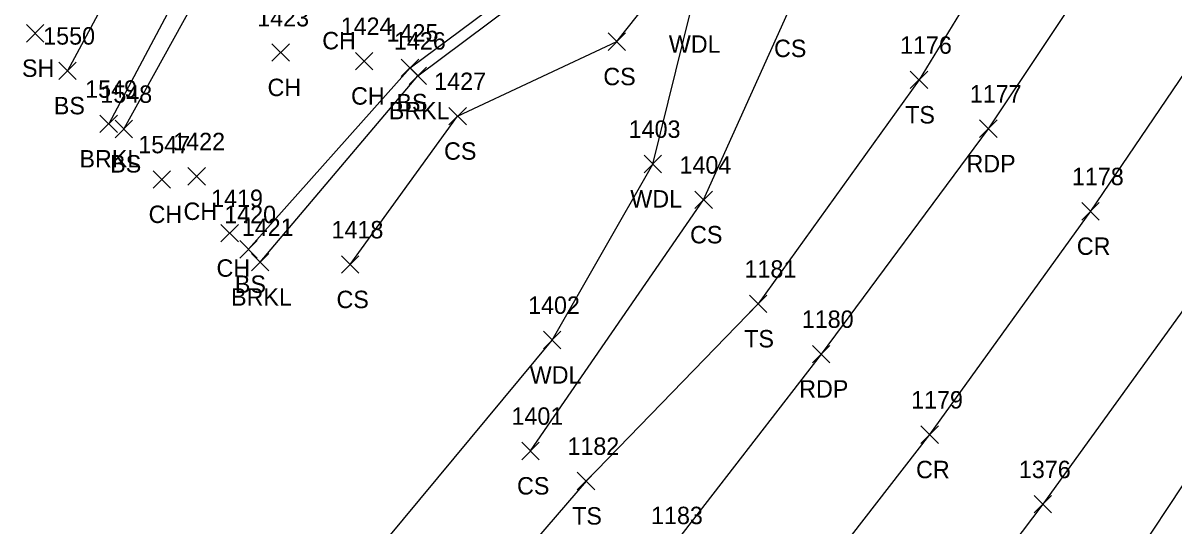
# Model space of a CAD drawing. Extents: x 1599840 to 1601211, y 518904 to 521989.
# Drawn here: x 1600682.8 to 1600815, y 521188.3 to 521246 of the extents above; entities that cross this region are included whole.
import ezdxf

# ---------------------------------------------------------------- set-up
doc = ezdxf.new("R2010")
doc.units = 0
for name, color, linetype in [('L_A', 7, 'Continuous'), ('L_I', 7, 'Continuous'), ('L_TIC', 7, 'Continuous'), ('LAWA', 7, 'Continuous'), ('LAWE', 7, 'Continuous'), ('LELB', 7, 'Continuous'), ('P_A', 7, 'Continuous'), ('P_I', 7, 'Continuous'), ('P_TIC', 7, 'Continuous'), ('PET', 7, 'Continuous'), ('PRC', 7, 'Continuous')]:
    doc.layers.add(name, color=color, linetype=linetype)

msp = doc.modelspace()

# ---------------------------------------------------------------- linework, layer by layer
at = {"layer": 'L_TIC'}
for points in [[(1600683.23, 521243.87), (1600685.23, 521245.87)], [(1600685.23, 521243.87), (1600683.23, 521245.87)], [(1600750.04, 521242.91), (1600752.04, 521244.91)], [(1600752.04, 521242.91), (1600750.04, 521244.91)], [(1600711.43, 521241.66), (1600713.43, 521243.66)], [(1600713.43, 521241.66), (1600711.43, 521243.66)], [(1600721.02, 521240.68), (1600723.02, 521242.68)], [(1600723.02, 521240.68), (1600721.02, 521242.68)], [(1600686.94, 521239.57), (1600688.94, 521241.57)], [(1600688.94, 521239.57), (1600686.94, 521241.57)], [(1600726.28, 521239.92), (1600728.28, 521241.92)], [(1600728.28, 521239.92), (1600726.28, 521241.92)], [(1600727.19, 521239), (1600729.19, 521241)], [(1600729.19, 521239), (1600727.19, 521241)], [(1600784.73, 521238.52), (1600786.73, 521240.52)], [(1600786.73, 521238.52), (1600784.73, 521240.52)], [(1600731.75, 521234.36), (1600733.75, 521236.36)], [(1600733.75, 521234.36), (1600731.75, 521236.36)], [(1600691.68, 521233.47), (1600693.68, 521235.47)], [(1600693.68, 521233.47), (1600691.68, 521235.47)], [(1600693.41, 521232.89), (1600695.41, 521234.89)], [(1600695.41, 521232.89), (1600693.41, 521234.89)], [(1600754.16, 521228.87), (1600756.16, 521230.87)], [(1600756.16, 521228.87), (1600754.16, 521230.87)], [(1600697.77, 521227.1), (1600699.77, 521229.1)], [(1600699.77, 521227.1), (1600697.77, 521229.1)], [(1600701.78, 521227.45), (1600703.78, 521229.45)], [(1600703.78, 521227.45), (1600701.78, 521229.45)], [(1600760, 521224.76), (1600762, 521226.76)], [(1600762, 521224.76), (1600760, 521226.76)], [(1600705.57, 521220.93), (1600707.57, 521222.93)], [(1600707.57, 521220.93), (1600705.57, 521222.93)], [(1600707.73, 521219.08), (1600709.73, 521221.08)], [(1600709.73, 521219.08), (1600707.73, 521221.08)], [(1600709.08, 521217.61), (1600711.08, 521219.61)], [(1600711.08, 521217.61), (1600709.08, 521219.61)], [(1600719.4, 521217.33), (1600721.4, 521219.33)], [(1600721.4, 521217.33), (1600719.4, 521219.33)], [(1600766.25, 521212.82), (1600768.25, 521214.82)], [(1600768.25, 521212.82), (1600766.25, 521214.82)], [(1600742.61, 521208.67), (1600744.61, 521210.67)], [(1600744.61, 521208.67), (1600742.61, 521210.67)], [(1600740.13, 521195.94), (1600742.13, 521197.94)], [(1600742.13, 521195.94), (1600740.13, 521197.94)], [(1600746.49, 521192.49), (1600748.49, 521194.49)], [(1600748.49, 521192.49), (1600746.49, 521194.49)]]:
    msp.add_lwpolyline(points, dxfattribs=at)
at = {"layer": 'LAWA'}
msp.add_lwpolyline([(1600715.26, 521175.56), (1600743.61, 521209.67), (1600755.16, 521229.87), (1600759.58, 521247.63)], dxfattribs=at)
at = {"layer": 'LAWE'}
for points in [[(1600788.5, 521302.13), (1600779.64, 521306.58), (1600769.85, 521311.78), (1600761.01, 521310.64), (1600751.78, 521307.23), (1600745.14, 521302.73), (1600731.02, 521295.66), (1600729.26, 521276.14), (1600716.1, 521262.82), (1600704.88, 521257.4), (1600692.68, 521234.47)], [(1600710.08, 521218.61), (1600728.19, 521240), (1600744.35, 521252.06), (1600761.88, 521257.58), (1600767.45, 521262.57), (1600777.03, 521264.85), (1600779.73, 521268.75)]]:
    msp.add_lwpolyline(points, dxfattribs=at)
at = {"layer": 'LELB'}
for points in [[(1600833.08, 521322.84), (1600827.14, 521306.56), (1600810.92, 521276.32), (1600800.69, 521262.52), (1600794.58, 521254.04), (1600785.73, 521239.52), (1600767.25, 521213.82), (1600747.49, 521193.49), (1600721.35, 521163.12)], [(1600741.13, 521196.94), (1600761, 521225.76), (1600770.64, 521247.14), (1600790.98, 521265.75), (1600800.28, 521274.95), (1600804.56, 521287.9), (1600802.13, 521291.13), (1600804.08, 521295.26), (1600810.48, 521300.32), (1600825.07, 521308.7)], [(1600708.73, 521220.08), (1600727.28, 521240.92), (1600743.42, 521252.91), (1600761.44, 521259.85), (1600768, 521266.83), (1600775.49, 521267.92), (1600778.3, 521269.52), (1600777.22, 521270.37), (1600777.98, 521271.94), (1600782.56, 521280.31), (1600784.37, 521283.66), (1600784.53, 521285.28), (1600784.99, 521289.18), (1600784.72, 521292.07), (1600785.2, 521295.05), (1600787.73, 521301.59)], [(1600732.33, 521294.56), (1600731.67, 521274), (1600718.47, 521262.22), (1600706.91, 521256.48), (1600694.41, 521233.89)], [(1600723.25, 521287.57), (1600703.93, 521270.27), (1600687.94, 521240.57)], [(1600720.4, 521218.33), (1600732.75, 521235.36), (1600751.04, 521243.91), (1600761.88, 521257.58)], [(1600819.4, 521198.14), (1600807.49, 521180.18), (1600800.87, 521166.44)]]:
    msp.add_lwpolyline(points, dxfattribs=at)
at = {"layer": 'P_TIC'}
for points in [[(1600792.69, 521232.92), (1600794.69, 521234.92)], [(1600794.69, 521232.92), (1600792.69, 521234.92)], [(1600804.42, 521223.44), (1600806.42, 521225.44)], [(1600806.42, 521223.44), (1600804.42, 521225.44)], [(1600773.49, 521207.06), (1600775.49, 521209.06)], [(1600775.49, 521207.06), (1600773.49, 521209.06)], [(1600785.95, 521197.81), (1600787.95, 521199.81)], [(1600787.95, 521197.81), (1600785.95, 521199.81)], [(1600798.95, 521189.82), (1600800.95, 521191.82)], [(1600800.95, 521189.82), (1600798.95, 521191.82)]]:
    msp.add_lwpolyline(points, dxfattribs=at)
at = {"layer": 'PET'}
for points in [[(1600925.83, 521507.52), (1600915.18, 521473.31), (1600903.26, 521440.28), (1600887.48, 521401.44), (1600873.35, 521370.15), (1600860.38, 521343.64), (1600847.93, 521319.69), (1600844.65, 521313.14), (1600836.72, 521299.9), (1600818.79, 521271.51), (1600793.69, 521233.92), (1600774.49, 521208.06), (1600757.09, 521185.54), (1600730.91, 521154.49)], [(1600955.79, 521499.34), (1600943.51, 521460.9), (1600932.49, 521430.95), (1600915.63, 521388.21), (1600902.46, 521359.92), (1600888.21, 521330.27), (1600876.23, 521308.06), (1600874.78, 521305.59), (1600851.3, 521265.61), (1600837.44, 521243.85), (1600825.08, 521225.62), (1600799.95, 521190.82), (1600794.12, 521183.15), (1600773.8, 521157.79), (1600751.79, 521131.81)]]:
    msp.add_lwpolyline(points, dxfattribs=at)
at = {"layer": 'PRC'}
msp.add_lwpolyline([(1600941.11, 521503.3), (1600929.22, 521466.1), (1600917.95, 521435.49), (1600901.05, 521394.76), (1600888.43, 521365.83), (1600873.97, 521336.55), (1600862.78, 521315.41), (1600848.88, 521291.08), (1600831.54, 521262.94), (1600805.42, 521224.44), (1600786.95, 521198.81), (1600768.67, 521175.32), (1600742.32, 521144.02)], dxfattribs=at)

# ---------------------------------------------------------------- texts
at = {"layer": 'L_A'}
for s, p in [('CH', (1600717.2, 521243.03)), ('WDL', (1600757, 521242.63)), ('CS', (1600769.08, 521242.14)), ('SH', (1600682.72, 521239.87)), ('CS', (1600749.48, 521238.91)), ('CH', (1600710.92, 521237.66)), ('CH', (1600720.51, 521236.68)), ('BS', (1600686.38, 521235.57)), ('BRKL', (1600724.84, 521235)), ('BS', (1600725.72, 521235.92)), ('TS', (1600784.14, 521234.52)), ('CS', (1600731.19, 521230.36)), ('BRKL', (1600689.32, 521229.47)), ('BS', (1600692.85, 521228.89)), ('WDL', (1600752.58, 521224.87)), ('CH', (1600697.26, 521223.1)), ('CH', (1600701.27, 521223.45)), ('CS', (1600759.44, 521220.76)), ('CH', (1600705.06, 521216.93)), ('BS', (1600707.17, 521215.08)), ('BRKL', (1600706.73, 521213.61)), ('CS', (1600718.84, 521213.33)), ('TS', (1600765.66, 521208.82)), ('WDL', (1600741.03, 521204.67)), ('CS', (1600739.57, 521191.94)), ('TS', (1600745.9, 521188.49))]:
    msp.add_text(s, height=2, dxfattribs=at).set_placement(p)
at = {"layer": 'L_I'}
for s, p in [('1423', (1600709.74, 521245.66)), ('1424', (1600719.32, 521244.68)), ('1550', (1600685.16, 521243.57)), ('1425', (1600724.59, 521243.92)), ('1426', (1600725.44, 521243)), ('1176', (1600783.55, 521242.52)), ('1549', (1600689.98, 521237.47)), ('1427', (1600730.06, 521238.36)), ('1548', (1600691.72, 521236.89)), ('1403', (1600752.39, 521232.87)), ('1547', (1600696.08, 521231.1)), ('1422', (1600700.09, 521231.45)), ('1404', (1600758.23, 521228.76)), ('1419', (1600704.44, 521224.93)), ('1420', (1600705.95, 521223.08)), ('1421', (1600707.96, 521221.61)), ('1418', (1600718.27, 521221.33)), ('1181', (1600765.69, 521216.82)), ('1402', (1600740.84, 521212.67)), ('1401', (1600738.93, 521199.94)), ('1182', (1600745.36, 521196.49))]:
    msp.add_text(s, height=2, dxfattribs=at).set_placement(p)
at = {"layer": 'P_A'}
for s, p in [('RDP', (1600791.18, 521228.92)), ('CR', (1600803.85, 521219.44)), ('RDP', (1600771.97, 521203.06)), ('CR', (1600785.39, 521193.81))]:
    msp.add_text(s, height=2, dxfattribs=at).set_placement(p)
at = {"layer": 'P_I'}
for s, p in [('1177', (1600791.56, 521236.92)), ('1178', (1600803.29, 521227.44)), ('1180', (1600772.27, 521211.06)), ('1179', (1600784.82, 521201.81)), ('1376', (1600797.2, 521193.82)), ('1183', (1600754.96, 521188.54))]:
    msp.add_text(s, height=2, dxfattribs=at).set_placement(p)

doc.saveas('drawing.dxf')
